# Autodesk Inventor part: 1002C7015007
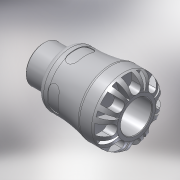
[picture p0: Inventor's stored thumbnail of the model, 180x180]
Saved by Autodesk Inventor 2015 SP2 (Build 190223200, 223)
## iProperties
Created: 2016-12
Part Number: 1002C7015007
Material: PVC-Piping
Description: PLASSON MALE COPPER ADAPTOR 15X3/4" SERIES 1 PLASSON MALE COPPER ADAPTOR 22X3/4" SERIES 1
Document SubType Name: Modeling
Designer: KIM
Mass: 78.119 g
Surface Area: 135.648 cm^2
Volume: 55.7993 cm^3
Density: 1.4 g/cm^3
Appearance: Smooth - White
Author: KIM
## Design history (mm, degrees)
derived "1002С.ipt"
feature "Solid1::1002С.ipt"
tag "TaggingFeature1"
body "Solid1"
other parameters: "d0" = 71, "d1" = 18.9, "d2" = 15, "d3" = 24.6, "d4" = 41, "d6" = 45, "d8" = 34.85, "d13" = 6.56, "d14" = 6.56, "d15" = 0, "d17" = 360 deg, "d19" = 8 deg, "d20" = 0.3, "d21" = 0.3, "d22" = 8 deg, "d24" = 0, "d26" = 360 deg, "d32" = 4.1, "d33" = 4.1, "d34" = 26.441, "d35" = 1.875, "d38" = 17, "d39" = 0.79323, "d42" = 6.97, "d43" = 4.51, "d45" = 17.444, "d46" = 0, "d59" = 360 deg, "d62" = 5.9245, "d63" = 0.3, "d65" = 0, "d66" = 0.41, "d_" = 15, "E_" = 41, "H_" = 71, "l_" = 45, "R_" = 26.441, "l_2" = 17, "d9" = 8.2, "d11" = 41, "d12" = 24.6
